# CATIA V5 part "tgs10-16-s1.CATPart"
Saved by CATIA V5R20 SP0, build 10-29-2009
Part number: TGS10-16-S1
Revision: 1
Definition: design
Nomenclature: TGS10-16-S1
Source: made
Description: NOT SPECIFIED
Bounding box of the stored display mesh (mm): x -22 to 0.8, y 0 to 10, z -4 to 4
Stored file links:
  C:\Users\Raffaele\Desktop\3D X SITO CF\I-MOLD\TGS-S1\tgs10-s1.step\tgs10-16-s1.CATPart
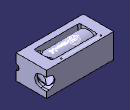
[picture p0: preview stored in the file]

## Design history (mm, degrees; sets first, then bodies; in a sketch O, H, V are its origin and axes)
Set1
  Line1 "LINE #4190": stored without definition
  DatumCurve1 "COMPOSITE_CURVE #4261"
  DatumCurve2 "COMPOSITE_CURVE #4312"
  DatumCurve3 "COMPOSITE_CURVE #4391"
  DatumCurve4 "COMPOSITE_CURVE #4434"
  DatumCurve5 "COMPOSITE_CURVE #4663"
  DatumCurve6 "COMPOSITE_CURVE #4805"
  DatumCurve7 "COMPOSITE_CURVE #4832"
  DatumCurve8 "COMPOSITE_CURVE #4890"
  DatumCurve9 "COMPOSITE_CURVE #4947"
  DatumCurve10 "COMPOSITE_CURVE #4976"
  DatumSurface1 "OPEN_SHELL #4180"
Body1 "MANIFOLD_SOLID_BREP #4181" (main body)
  Solid1: solid without history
